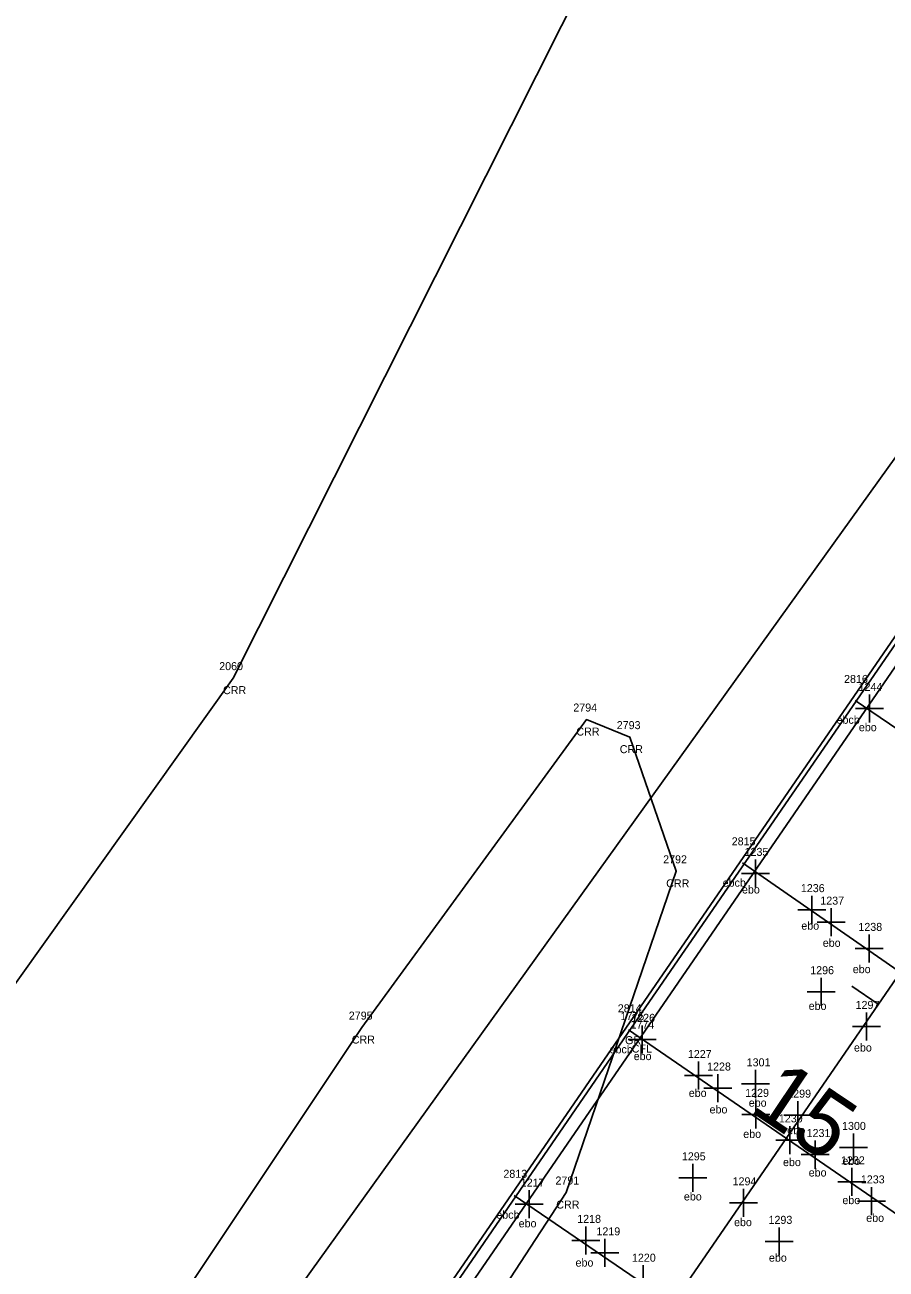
# Model space of a CAD drawing. Extents: x 2266664 to 2272542, y 716533 to 724777.
# Drawn here: x 2269061 to 2269168.6, y 720089.8 to 720245.2 of the extents above; entities that cross this region are included whole.
import ezdxf

# ---------------------------------------------------------------- set-up
doc = ezdxf.new("R2010")
doc.units = 0
for name, color, linetype in [('RD_EX_Bridge', 7, 'Continuous'), ('RD_EX_Conc', 7, 'Continuous'), ('RD_EX_Conc_txCode', 7, 'Continuous'), ('RD_EX_GuardRail', 7, 'Continuous'), ('RD_EX_GuardRail_txCode', 7, 'Continuous'), ('RD_EX_H2O', 7, 'Continuous'), ('RD_EX_H2O_txCode', 7, 'Continuous'), ('RD_EX_Misc', 7, 'Continuous'), ('RD_EX_Misc_txCode', 7, 'Continuous'), ('RD_EX_VEG', 7, 'Continuous'), ('RD_HC_Cl', 7, 'Continuous'), ('RD_HC_Data_Tic', 7, 'Continuous'), ('RD_HC_TX_Sta50', 7, 'Continuous'), ('RD_SMD_Locator', 7, 'Continuous')]:
    doc.layers.add(name, color=color, linetype=linetype)

msp = doc.modelspace()

# ---------------------------------------------------------------- linework, layer by layer
at = {"layer": 'RD_EX_Bridge'}
msp.add_lwpolyline([(2269005.71, 719844.75), (2269233.07, 720175.43), (2269193.18, 720202.86), (2268965.85, 719872.44), (2269005.71, 719844.75)], dxfattribs=at)
at = {"layer": 'RD_EX_Conc'}
msp.add_lwpolyline([(2268967.59, 719871.21), (2269010.36, 719933.37), (2269052.74, 719994.95), (2269096, 720057.76), (2269138.05, 720118.85), (2269194.93, 720201.62)], dxfattribs=at)
at = {"layer": 'RD_EX_GuardRail'}
msp.add_lwpolyline([(2268919.97, 719814.14), (2268926.75, 719820.52), (2268951.58, 719851.69), (2268966.29, 719871.68), (2268967.47, 719873.87), (2269009.19, 719934.42), (2269051.44, 719995.68), (2269094.56, 720058.42), (2269136.79, 720119.9), (2269193.57, 720202.38)], dxfattribs=at)
at = {"layer": 'RD_EX_H2O'}
for points in [[(2269381.9, 720672.38), (2269412.08, 720629.66), (2269382.2, 720610.29), (2269365.51, 720584.14), (2269325.11, 720482.65), (2269263.15, 720389.59), (2269192.33, 720305.7), (2269157.01, 720264.89), (2269134.41, 720257.7), (2269087.02, 720163.62), (2269039.79, 720097.47)], [(2269089.67, 720060.48), (2269103.31, 720060.56), (2269128.67, 720099.37), (2269142.41, 720139.49), (2269136.61, 720156.25), (2269131.18, 720158.45), (2269103.12, 720119.97), (2269073.45, 720075.52), (2269089.67, 720060.48)]]:
    msp.add_lwpolyline(points, dxfattribs=at)
at = {"layer": 'RD_EX_Misc'}
for p, q in [((2269166.55, 720161.58), (2269166.55, 720158.08)), ((2269203.97, 720134.11), (2269164.76, 720160.82)), ((2269168.3, 720159.83), (2269164.8, 720159.83)), ((2269189.73, 720113.5), (2269150.7, 720140.54)), ((2269152.31, 720140.97), (2269152.31, 720137.47)), ((2269154.06, 720139.22), (2269150.56, 720139.22)), ((2269159.36, 720136.45), (2269159.36, 720132.95)), ((2269161.77, 720134.88), (2269161.77, 720131.38)), ((2269161.11, 720134.7), (2269157.61, 720134.7)), ((2269163.52, 720133.13), (2269160.02, 720133.13)), ((2269166.53, 720131.6), (2269166.53, 720128.1)), ((2269168.28, 720129.85), (2269164.78, 720129.85)), ((2269160.53, 720126.19), (2269160.53, 720122.69)), ((2269162.28, 720124.44), (2269158.78, 720124.44)), ((2269166.18, 720121.85), (2269166.18, 720118.35)), ((2269175.58, 720092.77), (2269136.46, 720119.68)), ((2269138.16, 720120.24), (2269138.16, 720116.74)), ((2269167.93, 720120.1), (2269164.43, 720120.1)), ((2269139.91, 720118.49), (2269136.41, 720118.49)), ((2269145.21, 720115.72), (2269145.21, 720112.22)), ((2269152.33, 720114.68), (2269152.33, 720111.18)), ((2269146.96, 720113.97), (2269143.46, 720113.97)), ((2269147.62, 720114.16), (2269147.62, 720110.66)), ((2269149.37, 720112.41), (2269145.87, 720112.41)), ((2269154.08, 720112.93), (2269150.58, 720112.93)), ((2269152.38, 720110.87), (2269152.38, 720107.37)), ((2269157.63, 720110.77), (2269157.63, 720107.27)), ((2269154.13, 720109.12), (2269150.63, 720109.12)), ((2269159.38, 720109.02), (2269155.88, 720109.02)), ((2269156.63, 720107.68), (2269156.63, 720104.18)), ((2269158.38, 720105.93), (2269154.88, 720105.93)), ((2269159.77, 720105.85), (2269159.77, 720102.35)), ((2269164.57, 720106.74), (2269164.57, 720103.24)), ((2269161.52, 720104.1), (2269158.02, 720104.1)), ((2269166.32, 720104.99), (2269162.82, 720104.99)), ((2269144.47, 720102.94), (2269144.47, 720099.44)), ((2269164.36, 720102.44), (2269164.36, 720098.94)), ((2269146.22, 720101.19), (2269142.72, 720101.19)), ((2269166.11, 720100.69), (2269162.61, 720100.69)), ((2269124.05, 720099.65), (2269124.05, 720096.15)), ((2269150.81, 720099.82), (2269150.81, 720096.32)), ((2269166.84, 720100.06), (2269166.84, 720096.56)), ((2269161.46, 720072.18), (2269122.16, 720099.01)), ((2269125.8, 720097.9), (2269122.3, 720097.9)), ((2269152.56, 720098.07), (2269149.06, 720098.07)), ((2269168.59, 720098.31), (2269165.09, 720098.31)), ((2269131.1, 720095.13), (2269131.1, 720091.63)), ((2269155.3, 720095.01), (2269155.3, 720091.51)), ((2269132.85, 720093.38), (2269129.35, 720093.38)), ((2269133.5, 720093.57), (2269133.5, 720090.07)), ((2269157.05, 720093.26), (2269153.55, 720093.26)), ((2269135.25, 720091.82), (2269131.75, 720091.82)), ((2269138.27, 720090.28), (2269138.27, 720086.78))]:
    msp.add_line(p, q, dxfattribs=at)
at = {"layer": 'RD_EX_VEG'}
msp.add_lwpolyline([(2268819.78, 719716.8), (2268871.54, 719776.21), (2269193.85, 720224.65), (2269408.57, 720538.5), (2269589.67, 720791.77), (2270047.56, 721479.8), (2270363.13, 721951.09), (2270746.65, 722498.38), (2270919.94, 722752.82), (2271017.26, 722923.37)], dxfattribs=at)
at = {"layer": 'RD_HC_Cl'}
msp.add_line((2267342.91, 717471.2), (2272360.46, 724762.59), dxfattribs=at)
at = {"layer": 'RD_HC_Data_Tic'}
msp.add_line((2269167.67, 720122.9), (2269164.37, 720125.16), dxfattribs=at)
at = {"layer": 'RD_SMD_Locator'}
for centre in [(2269087.02, 720163.62), (2269131.18, 720158.45), (2269136.61, 720156.25), (2269142.41, 720139.49), (2269103.12, 720119.97), (2269136.79, 720119.9), (2269138.05, 720118.85), (2269128.67, 720099.37)]:
    msp.add_circle(centre, 0.001, dxfattribs=at)

# ---------------------------------------------------------------- texts
at = {"layer": 'RD_EX_Conc_txCode'}
for s, p in [('1774', (2269136.71, 720119.85)), ('CFL', (2269136.85, 720116.85))]:
    msp.add_text(s, height=1, dxfattribs=at).set_placement(p)
at = {"layer": 'RD_EX_GuardRail_txCode'}
for s, p in [('1775', (2269135.45, 720120.9)), ('GR', (2269136.01, 720117.9))]:
    msp.add_text(s, height=1, dxfattribs=at).set_placement(p)
at = {"layer": 'RD_EX_H2O_txCode'}
for s, p in [('2060', (2269085.29, 720164.62)), ('CRR', (2269085.77, 720161.62)), ('2794', (2269129.55, 720159.45)), ('2793', (2269134.98, 720157.25)), ('CRR', (2269129.93, 720156.45)), ('CRR', (2269135.36, 720154.25)), ('2792', (2269140.78, 720140.49)), ('CRR', (2269141.16, 720137.49)), ('2795', (2269101.49, 720120.97)), ('CRR', (2269101.86, 720117.97)), ('2791', (2269127.32, 720100.37)), ('CRR', (2269127.42, 720097.37))]:
    msp.add_text(s, height=1, dxfattribs=at).set_placement(p)
at = {"layer": 'RD_EX_Misc_txCode'}
for s, p in [('2816', (2269163.39, 720163.02)), ('1244', (2269165.21, 720162.03)), ('ebcb', (2269162.45, 720157.92)), ('ebo', (2269165.24, 720156.99)), ('2815', (2269149.35, 720142.74)), ('1235', (2269150.96, 720141.42)), ('ebcb', (2269148.22, 720137.57)), ('ebo', (2269150.63, 720136.72)), ('1236', (2269157.99, 720136.89)), ('1237', (2269160.42, 720135.33)), ('ebo', (2269158.05, 720132.2)), ('1238', (2269165.18, 720132.05)), ('ebo', (2269160.73, 720130.06)), ('1296', (2269159.16, 720126.64)), ('ebo', (2269164.48, 720126.77)), ('2814', (2269135.11, 720121.88)), ('ebo', (2269158.97, 720122.18)), ('1297', (2269164.83, 720122.3)), ('1226', (2269136.79, 720120.69)), ('ebcb', (2269134.08, 720116.76)), ('ebo', (2269164.63, 720116.98)), ('ebo', (2269137.1, 720115.91)), ('1227', (2269143.87, 720116.17)), ('1228', (2269146.27, 720114.61)), ('1301', (2269151.22, 720115.13)), ('ebo', (2269143.98, 720111.31)), ('1229', (2269151.03, 720111.32)), ('1299', (2269156.29, 720111.22)), ('ebo', (2269146.58, 720109.25)), ('ebo', (2269151.48, 720110.09)), ('1230', (2269155.24, 720108.13)), ('ebo', (2269150.79, 720106.19)), ('ebo', (2269156.29, 720106.65)), ('1231', (2269158.71, 720106.3)), ('1300', (2269163.14, 720107.19)), ('1295', (2269143.12, 720103.39)), ('1232', (2269163.01, 720102.89)), ('ebo', (2269163.18, 720102.82)), ('ebo', (2269155.76, 720102.67)), ('ebo', (2269158.97, 720101.37)), ('2813', (2269120.81, 720101.21)), ('1217', (2269122.98, 720100.1)), ('1294', (2269149.46, 720100.27)), ('1233', (2269165.49, 720100.51)), ('ebo', (2269143.37, 720098.38)), ('ebo', (2269163.18, 720097.92)), ('ebcb', (2269119.93, 720096.1)), ('ebo', (2269122.72, 720095.02)), ('1218', (2269130.04, 720095.58)), ('ebo', (2269149.64, 720095.17)), ('1293', (2269153.95, 720095.46)), ('ebo', (2269166.16, 720095.7)), ('1219', (2269132.44, 720094.02)), ('1220', (2269136.88, 720090.73)), ('ebo', (2269154, 720090.73)), ('ebo', (2269129.83, 720090.12))]:
    msp.add_text(s, height=1, dxfattribs=at).set_placement(p)
at = {"layer": 'RD_HC_TX_Sta50'}
msp.add_text('15', height=8, rotation=326.0703, dxfattribs=at).set_placement((2269151.39, 720109.66))

doc.saveas('drawing.dxf')
